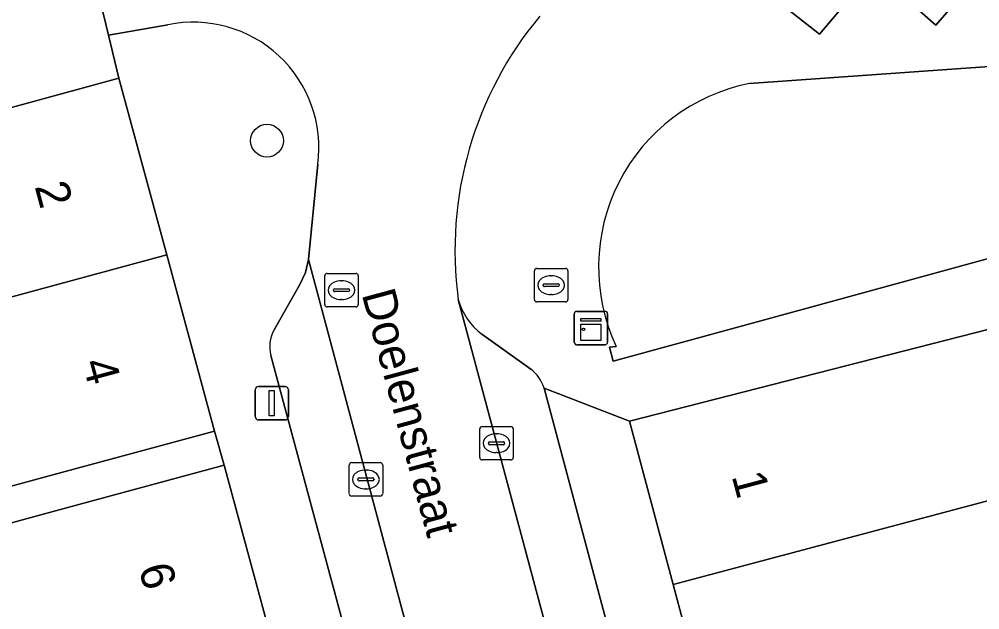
# Model space of a CAD drawing. Extents: x 159262 to 160143, y 383399 to 384319.
# Drawn here: x 159630.85 to 159659.54, y 383760.7 to 383778.34 of the extents above; entities that cross this region are included whole.
import ezdxf

# ---------------------------------------------------------------- set-up
doc = ezdxf.new("R2010")
doc.units = 0
for name, color, linetype in [('IMGEO_Boom', 7, 'Continuous'), ('IMGEO_Brandkraan', 7, 'Continuous'), ('IMGEO_Erf', 7, 'Continuous'), ('IMGEO_Groenvoorziening', 7, 'Continuous'), ('IMGEO_Kast', 7, 'Continuous'), ('IMGEO_Kolk', 7, 'Continuous'), ('IMGEO_Lichtmast', 7, 'Continuous'), ('IMGEO_Openbare_ruimte_label', 7, 'Continuous'), ('IMGEO_Pand', 7, 'Continuous'), ('IMGEO_Pand_nummerreeks', 7, 'Continuous'), ('IMGEO_Parkeervlak_open', 7, 'Continuous'), ('IMGEO_Rijbaan_lokaal_open', 7, 'Continuous'), ('IMGEO_Rioolput', 7, 'Continuous'), ('IMGEO_Voetpad_open', 7, 'Continuous')]:
    doc.layers.add(name, color=color, linetype=linetype)

msp = doc.modelspace()

# ---------------------------------------------------------------- linework, layer by layer
at = {"layer": 'IMGEO_Boom'}
msp.add_circle((159638.248, 383774.709), 0.489, dxfattribs=at)
at = {"layer": 'IMGEO_Brandkraan'}
for p, q in [((159646.237, 383769.968), (159646.237, 383770.82)), ((159646.312, 383770.894), (159647.164, 383770.894)), ((159647.238, 383770.82), (159647.238, 383769.968)), ((159646.496, 383770.388), (159646.496, 383770.4)), ((159646.539, 383770.437), (159646.937, 383770.437)), ((159646.725, 383770.674), (159646.75, 383770.674)), ((159646.98, 383770.4), (159646.98, 383770.388)), ((159646.934, 383770.351), (159646.536, 383770.351)), ((159646.748, 383770.114), (159646.723, 383770.114)), ((159647.164, 383769.894), (159646.312, 383769.894))]:
    msp.add_line(p, q, dxfattribs=at)
for points in [[(159646.237, 383769.968), (159646.237, 383770.82)], [(159646.312, 383770.894), (159647.164, 383770.894)], [(159647.238, 383770.82), (159647.238, 383769.968)], [(159647.164, 383769.894), (159646.312, 383769.894)]]:
    msp.add_lwpolyline(points, dxfattribs=at)
for centre, radius, start, end in [((159646.314, 383770.818), 0.0765, 91.552, 178.448), ((159646.314, 383770.818), 0.0765, 91.552, 178.448), ((159647.162, 383770.818), 0.0765, 1.552, 88.448), ((159647.162, 383770.818), 0.0765, 1.552, 88.448), ((159646.536, 383770.397), 0.0403, 85.8775, 175.7526), ((159646.941, 383770.399), 0.0386, 1.7309, 96.639), ((159646.533, 383770.387), 0.0366, 178.938, 274.7102), ((159646.937, 383770.394), 0.043, 264.8664, 352.4533), ((159646.314, 383769.97), 0.0765, 181.552, 268.448), ((159646.314, 383769.97), 0.0765, 181.552, 268.448), ((159647.162, 383769.97), 0.0765, 271.552, 358.448), ((159647.162, 383769.97), 0.0765, 271.552, 358.448)]:
    msp.add_arc(centre, radius, start, end, dxfattribs=at)
for centre, major_axis, ratio, start_param, end_param in [((159646.724, 383770.394), (-0.387, 0.002), 0.722429, 4.712389, 7.853982), ((159646.749, 383770.394), (-0.39, 0.002), 0.717154, 1.570796, 4.712389)]:
    msp.add_ellipse(centre, major_axis=major_axis, ratio=ratio, start_param=start_param, end_param=end_param, dxfattribs=at)
at = {"layer": 'IMGEO_Erf'}
for points in [[(159629.001, 383775.267), (159633.827, 383776.573), (159633.517, 383777.856), (159632.571, 383781.773), (159632.485, 383782.13), (159631.623, 383783.36), (159624.332, 383782.581)], [(159628.564, 383762.742), (159632.148, 383763.712), (159636.974, 383765.018), (159636.68, 383766.03), (159631.854, 383764.724), (159627.598, 383763.573)]]:
    msp.add_lwpolyline(points, dxfattribs=at)
at = {"layer": 'IMGEO_Groenvoorziening'}
for points in [[(159648.681, 383768.565), (159648.477, 383768.54), (159648.592, 383768.122), (159654.492, 383769.739), (159673.642, 383774.987), (159672.72, 383777.877)], [(159672.72, 383777.877), (159659.837, 383776.925), (159652.662, 383776.415)]]:
    msp.add_lwpolyline(points, dxfattribs=at)
msp.add_arc((159653.741, 383770.934), 5.587, 101.1328, 205.085, dxfattribs=at)
at = {"layer": 'IMGEO_Kast'}
for p, q in [((159647.425, 383768.687), (159647.425, 383769.528)), ((159647.425, 383769.528), (159647.425, 383768.687)), ((159647.5, 383769.612), (159648.341, 383769.612)), ((159648.341, 383769.612), (159647.5, 383769.612)), ((159648.425, 383769.537), (159648.425, 383768.696)), ((159648.425, 383768.696), (159648.425, 383769.537)), ((159648.35, 383768.612), (159647.509, 383768.612)), ((159647.509, 383768.612), (159648.35, 383768.612))]:
    msp.add_line(p, q, dxfattribs=at)
for points in [[(159647.62, 383769.402), (159648.22, 383769.402), (159648.22, 383769.317), (159647.62, 383769.317), (159647.62, 383769.402)], [(159647.62, 383769.227), (159648.22, 383769.227), (159648.22, 383768.738), (159647.62, 383768.738), (159647.62, 383769.227)]]:
    msp.add_lwpolyline(points, dxfattribs=at)
msp.add_circle((159647.704, 383769.076), 0.0377, dxfattribs=at)
for centre, start, end in [((159647.503, 383769.534), 92.4484, 184.2845), ((159647.503, 383769.534), 92.4484, 184.2845), ((159648.347, 383769.534), 2.4484, 94.2845), ((159648.347, 383769.534), 2.4484, 94.2845), ((159647.503, 383768.69), 182.4484, 274.2845), ((159647.503, 383768.69), 182.4484, 274.2845), ((159648.347, 383768.69), 272.4484, 4.2845), ((159648.347, 383768.69), 272.4484, 4.2845)]:
    msp.add_arc(centre, 0.0779, start, end, dxfattribs=at)
at = {"layer": 'IMGEO_Kolk'}
for p, q in [((159644.604, 383765.246), (159644.604, 383766.098)), ((159644.679, 383766.172), (159645.531, 383766.172)), ((159645.605, 383766.098), (159645.605, 383765.246)), ((159645.092, 383765.952), (159645.117, 383765.952)), ((159644.863, 383765.666), (159644.863, 383765.678)), ((159645.301, 383765.629), (159644.903, 383765.629)), ((159644.906, 383765.715), (159645.304, 383765.715)), ((159645.347, 383765.678), (159645.347, 383765.666)), ((159645.115, 383765.392), (159645.09, 383765.392)), ((159640.704, 383764.166), (159640.704, 383765.018)), ((159640.779, 383765.092), (159641.631, 383765.092)), ((159641.705, 383765.018), (159641.705, 383764.166)), ((159645.531, 383765.172), (159644.679, 383765.172)), ((159641.192, 383764.872), (159641.217, 383764.872)), ((159640.963, 383764.586), (159640.963, 383764.598)), ((159641.401, 383764.549), (159641.003, 383764.549)), ((159641.006, 383764.635), (159641.404, 383764.635)), ((159641.447, 383764.598), (159641.447, 383764.586)), ((159641.631, 383764.092), (159640.779, 383764.092)), ((159641.215, 383764.312), (159641.19, 383764.312))]:
    msp.add_line(p, q, dxfattribs=at)
for points in [[(159644.604, 383765.246), (159644.604, 383766.098)], [(159644.679, 383766.172), (159645.531, 383766.172)], [(159645.605, 383766.098), (159645.605, 383765.246)], [(159640.704, 383764.166), (159640.704, 383765.018)], [(159640.779, 383765.092), (159641.631, 383765.092)], [(159641.705, 383765.018), (159641.705, 383764.166)], [(159645.531, 383765.172), (159644.679, 383765.172)], [(159641.631, 383764.092), (159640.779, 383764.092)]]:
    msp.add_lwpolyline(points, dxfattribs=at)
for centre, radius, start, end in [((159644.681, 383766.096), 0.0765, 91.552, 178.448), ((159644.681, 383766.096), 0.0765, 91.552, 178.448), ((159645.529, 383766.096), 0.0765, 1.552, 88.448), ((159645.529, 383766.096), 0.0765, 1.552, 88.448), ((159644.903, 383765.675), 0.0403, 85.8775, 175.7526), ((159644.9, 383765.665), 0.0366, 178.938, 274.7102), ((159645.304, 383765.672), 0.043, 264.8664, 352.4533), ((159645.308, 383765.677), 0.0386, 1.7309, 96.639), ((159644.681, 383765.248), 0.0765, 181.552, 268.448), ((159644.681, 383765.248), 0.0765, 181.552, 268.448), ((159645.529, 383765.248), 0.0765, 271.552, 358.448), ((159645.529, 383765.248), 0.0765, 271.552, 358.448), ((159640.781, 383765.016), 0.0765, 91.552, 178.448), ((159640.781, 383765.016), 0.0765, 91.552, 178.448), ((159641.629, 383765.016), 0.0765, 1.552, 88.448), ((159641.629, 383765.016), 0.0765, 1.552, 88.448), ((159641.003, 383764.595), 0.0403, 85.8775, 175.7526), ((159641, 383764.585), 0.0366, 178.938, 274.7102), ((159641.404, 383764.592), 0.043, 264.8664, 352.4533), ((159641.408, 383764.597), 0.0386, 1.7309, 96.639), ((159640.781, 383764.168), 0.0765, 181.552, 268.448), ((159640.781, 383764.168), 0.0765, 181.552, 268.448), ((159641.629, 383764.168), 0.0765, 271.552, 358.448), ((159641.629, 383764.168), 0.0765, 271.552, 358.448)]:
    msp.add_arc(centre, radius, start, end, dxfattribs=at)
for centre, major_axis, ratio, start_param, end_param in [((159645.091, 383765.672), (-0.387, 0.002), 0.722429, 4.712389, 7.853982), ((159645.116, 383765.672), (-0.39, 0.002), 0.717154, 1.570796, 4.712389), ((159641.191, 383764.592), (-0.387, 0.002), 0.722429, 4.712389, 7.853982), ((159641.216, 383764.592), (-0.39, 0.002), 0.717154, 1.570796, 4.712389)]:
    msp.add_ellipse(centre, major_axis=major_axis, ratio=ratio, start_param=start_param, end_param=end_param, dxfattribs=at)
at = {"layer": 'IMGEO_Lichtmast'}
for p, q in [((159637.897, 383766.468), (159637.897, 383767.268)), ((159637.897, 383767.268), (159637.897, 383766.468)), ((159637.997, 383767.368), (159638.787, 383767.368)), ((159638.787, 383767.368), (159637.997, 383767.368)), ((159638.887, 383767.268), (159638.887, 383766.468)), ((159638.887, 383766.468), (159638.887, 383767.268)), ((159638.787, 383766.368), (159637.997, 383766.368)), ((159637.997, 383766.368), (159638.787, 383766.368))]:
    msp.add_line(p, q, dxfattribs=at)
msp.add_lwpolyline([(159638.317, 383767.243), (159638.467, 383767.243), (159638.467, 383766.493), (159638.317, 383766.493), (159638.317, 383767.243)], dxfattribs=at)
for centre, start, end in [((159637.997, 383767.268), 90, 180), ((159637.997, 383767.268), 90, 180), ((159638.787, 383767.268), 0, 90), ((159638.787, 383767.268), 360, 90), ((159637.997, 383766.468), 180, 270), ((159637.997, 383766.468), 180, 270), ((159638.787, 383766.468), 270, 0), ((159638.787, 383766.468), 270, 0)]:
    msp.add_arc(centre, 0.1, start, end, dxfattribs=at)
at = {"layer": 'IMGEO_Pand'}
for points in [[(159633.827, 383776.573), (159629.001, 383775.267), (159616.207, 383771.806), (159616.932, 383769.125), (159615.883, 383768.841), (159616.279, 383766.065), (159620.663, 383767.251), (159619.936, 383769.938), (159625.47, 383771.436), (159626.172, 383768.843), (159635.253, 383771.302)], [(159635.253, 383771.302), (159626.172, 383768.843), (159627.598, 383763.573), (159631.854, 383764.724), (159636.68, 383766.03)], [(159662.757, 383767.379), (159660.437, 383766.761), (159660.117, 383767.961), (159659.819, 383769.08), (159649.082, 383766.334), (159650.383, 383761.448), (159663.412, 383764.92)], [(159636.974, 383765.018), (159632.148, 383763.712), (159628.564, 383762.742), (159629.907, 383757.78), (159633.491, 383758.75), (159638.317, 383760.056)], [(159664.041, 383762.557), (159663.412, 383764.92), (159650.383, 383761.448), (159651.684, 383756.561), (159656.516, 383757.847), (159659.929, 383758.756), (159662.178, 383759.355), (159661.505, 383761.882)]]:
    msp.add_lwpolyline(points, close=True, dxfattribs=at)
at = {"layer": 'IMGEO_Parkeervlak_open'}
for points in [[(159654.722, 383781.481), (159652.947, 383779.318), (159654.753, 383777.895), (159656.371, 383779.805), (159658.227, 383778.164), (159659.866, 383780.052), (159661.711, 383778.433), (159663.401, 383780.297), (159665.296, 383778.693), (159666.913, 383780.605), (159668.734, 383778.911), (159672.412, 383783.446)], [(159658.957, 383698.358), (159656.262, 383708.47), (159655.531, 383711.127), (159639.486, 383771.164), (159639.401, 383770.773), (159639.228, 383770.41), (159638.462, 383769.062)], [(159643.962, 383769.967), (159659.468, 383712.142), (159660.175, 383709.486), (159675.226, 383653.663), (159677.362, 383645.771), (159683.923, 383621.261), (159685.312, 383616.758), (159691.977, 383598.671)], [(159646.126, 383767.887), (159644.666, 383768.928)], [(159638.359, 383768.29), (159643.296, 383750), (159643.745, 383748.335), (159644.756, 383744.665), (159650.603, 383722.664), (159651.489, 383719.443), (159656.5, 383700.639)], [(159693.06, 383602.465), (159688.816, 383614.013), (159688.233, 383613.793), (159688.041, 383614.333), (159686.892, 383617.599), (159685.869, 383620.959), (159685.195, 383623.453), (159683.304, 383630.406), (159681.505, 383637.111), (159680.482, 383640.885), (159670.837, 383676.812), (159669.809, 383680.581), (159656.528, 383729.905), (159655.419, 383734.157), (159651.173, 383750), (159650.479, 383752.591), (159649.37, 383756.675), (159646.528, 383767.317)]]:
    msp.add_lwpolyline(points, dxfattribs=at)
for centre, radius, start, end in [((159645.873, 383770.504), 1.985, 195.6925, 232.5486), ((159639.387, 383768.546), 1.059, 150.8314, 193.9695), ((159645.385, 383766.938), 1.204, 18.3572, 52.0306)]:
    msp.add_arc(centre, radius, start, end, dxfattribs=at)
at = {"layer": 'IMGEO_Rijbaan_lokaal_open'}
for points in [[(159632.485, 383782.13), (159632.571, 383781.773), (159633.517, 383777.856), (159635.289, 383778.169)], [(159639.765, 383774.003), (159639.486, 383771.164), (159655.531, 383711.127), (159659.468, 383712.142), (159643.962, 383769.967)]]:
    msp.add_lwpolyline(points, dxfattribs=at)
for centre, radius, start, end in [((159654.782, 383771.433), 10.919, 140.1683, 187.7174), ((159636.053, 383774.502), 3.746, 352.3422, 101.7666)]:
    msp.add_arc(centre, radius, start, end, dxfattribs=at)
at = {"layer": 'IMGEO_Rioolput'}
for p, q in [((159640.048, 383770.744), (159640.9, 383770.744)), ((159639.973, 383769.818), (159639.973, 383770.67)), ((159640.461, 383770.524), (159640.486, 383770.524)), ((159640.974, 383770.67), (159640.974, 383769.818)), ((159640.232, 383770.238), (159640.232, 383770.25)), ((159640.67, 383770.201), (159640.272, 383770.201)), ((159640.275, 383770.287), (159640.673, 383770.287)), ((159640.716, 383770.25), (159640.716, 383770.238)), ((159640.484, 383769.964), (159640.459, 383769.964)), ((159640.9, 383769.744), (159640.048, 383769.744))]:
    msp.add_line(p, q, dxfattribs=at)
for points in [[(159640.048, 383770.744), (159640.9, 383770.744)], [(159639.973, 383769.818), (159639.973, 383770.67)], [(159640.974, 383770.67), (159640.974, 383769.818)], [(159640.9, 383769.744), (159640.048, 383769.744)]]:
    msp.add_lwpolyline(points, dxfattribs=at)
for centre, radius, start, end in [((159640.05, 383770.668), 0.0765, 91.552, 178.448), ((159640.05, 383770.668), 0.0765, 91.552, 178.448), ((159640.898, 383770.668), 0.0765, 1.552, 88.448), ((159640.898, 383770.668), 0.0765, 1.552, 88.448), ((159640.272, 383770.247), 0.0403, 85.8775, 175.7526), ((159640.269, 383770.237), 0.0366, 178.938, 274.7102), ((159640.673, 383770.244), 0.043, 264.8664, 352.4533), ((159640.677, 383770.249), 0.0386, 1.7309, 96.639), ((159640.05, 383769.82), 0.0765, 181.552, 268.448), ((159640.05, 383769.82), 0.0765, 181.552, 268.448), ((159640.898, 383769.82), 0.0765, 271.552, 358.448), ((159640.898, 383769.82), 0.0765, 271.552, 358.448)]:
    msp.add_arc(centre, radius, start, end, dxfattribs=at)
for centre, major_axis, ratio, start_param, end_param in [((159640.46, 383770.244), (-0.387, 0.002), 0.722429, 4.712389, 7.853982), ((159640.485, 383770.244), (-0.39, 0.002), 0.717154, 1.570796, 4.712389)]:
    msp.add_ellipse(centre, major_axis=major_axis, ratio=ratio, start_param=start_param, end_param=end_param, dxfattribs=at)
at = {"layer": 'IMGEO_Voetpad_open'}
for points in [[(159646.528, 383767.317), (159649.082, 383766.334), (159659.819, 383769.08), (159671.622, 383772.279), (159678.526, 383774.149), (159678.999, 383774.269), (159678.024, 383784.425)], [(159672.412, 383783.446), (159668.734, 383778.911), (159666.913, 383780.605), (159665.296, 383778.693), (159663.401, 383780.297), (159661.711, 383778.433), (159659.866, 383780.052), (159658.227, 383778.164), (159656.371, 383779.805), (159654.753, 383777.895), (159652.947, 383779.318), (159654.722, 383781.481)], [(159635.289, 383778.169), (159633.517, 383777.856), (159633.827, 383776.573), (159635.253, 383771.302), (159636.68, 383766.03), (159636.974, 383765.018), (159638.317, 383760.056), (159638.565, 383759.062), (159640.137, 383753.253), (159640.446, 383751.999), (159640.982, 383750), (159642.491, 383744.379), (159644.171, 383738.119), (159644.416, 383737.077), (159645.621, 383732.59), (159645.865, 383731.643), (159647.329, 383726.195), (159648.76, 383720.87)], [(159672.72, 383777.877), (159673.642, 383774.987), (159654.492, 383769.739), (159648.592, 383768.122), (159648.477, 383768.54), (159648.681, 383768.565)], [(159652.662, 383776.415), (159659.837, 383776.925), (159672.72, 383777.877)], [(159638.462, 383769.062), (159639.228, 383770.41), (159639.401, 383770.773), (159639.486, 383771.164), (159639.765, 383774.003)], [(159644.666, 383768.928), (159646.126, 383767.887)], [(159656.5, 383700.639), (159651.489, 383719.443), (159650.486, 383719.167), (159649.6, 383722.388), (159650.603, 383722.664), (159644.756, 383744.665), (159643.753, 383744.389), (159642.742, 383748.059), (159643.745, 383748.335), (159643.296, 383750), (159638.359, 383768.29)], [(159660.182, 383724.724), (159659.933, 383725.661), (159658.411, 383731.343), (159657.866, 383733.363), (159656.036, 383740.193), (159655.705, 383741.589), (159654.007, 383747.895), (159653.44, 383750), (159652.309, 383754.199), (159651.684, 383756.561), (159650.383, 383761.448), (159649.082, 383766.334), (159646.528, 383767.317), (159649.37, 383756.675), (159650.374, 383756.948), (159651.483, 383752.864), (159650.479, 383752.591), (159651.173, 383750), (159655.419, 383734.157), (159656.425, 383734.419), (159657.534, 383730.167), (159656.528, 383729.905), (159669.809, 383680.581)]]:
    msp.add_lwpolyline(points, dxfattribs=at)
for centre, radius, start, end in [((159654.782, 383771.433), 10.919, 140.1683, 187.7174), ((159636.053, 383774.502), 3.746, 352.3422, 101.7666), ((159653.741, 383770.934), 5.587, 101.1328, 205.085), ((159645.873, 383770.504), 1.985, 195.6925, 232.5486), ((159639.387, 383768.546), 1.059, 150.8314, 193.9695), ((159645.385, 383766.938), 1.204, 18.3572, 52.0306)]:
    msp.add_arc(centre, radius, start, end, dxfattribs=at)

# ---------------------------------------------------------------- texts
at = {"layer": 'IMGEO_Openbare_ruimte_label'}
msp.add_text('Doelenstraat', height=1, rotation=285.1345, dxfattribs=at).set_placement((159641.072, 383770.13))
at = {"layer": 'IMGEO_Pand_nummerreeks'}
for s, rotation, p in [('2', 285.1431, (159631.302, 383773.348)), ('4', 285.1419, (159632.728, 383768.075)), ('1', 284.9082, (159652.126, 383764.695)), ('6', 285.1447, (159634.407, 383761.945))]:
    msp.add_text(s, height=1, rotation=rotation, dxfattribs=at).set_placement(p)

doc.saveas('drawing.dxf')
